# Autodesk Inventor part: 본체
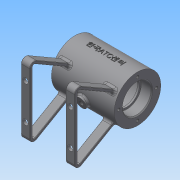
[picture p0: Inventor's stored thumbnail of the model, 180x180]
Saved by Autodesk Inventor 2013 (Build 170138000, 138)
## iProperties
Created: 2016-03
Part Number: 본체
Material: 일반
Document SubType Name: Modeling
Designer: Administrator
Density: 1 g/cm^3
Author: Administrator
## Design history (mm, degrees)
sketch "스케치1"
  geometry: L1 (0, 21)-(21, 21); L2 (21, 21)-(21, 14); L3 (21, 14)-(23, 14); L4 (23, 14)-(23, 16); L5 (23, 16)-(35, 16); L6 (35, 16)-(35, 26); L7 (35, 26)-(0, 26); L8 (0, 26)-(0, 21); L9 (0, 0)-(35, 0)
  constraints: 18 end point, 5 parallel, 3 perpendicular, 1 horizontal, 1 point on line
  dimensions: "d0" = 35 distance of L9.start L9.end; "d2" = 12 distance of L4.end L5.end; "d3" = 2 distance of L2.end L3.end; "d4" = 21 distance of L1.start L1.end; "d6" = 32 diameter of L5 L9; "d7" = 28 diameter of L3 L9; "d8" = 42 diameter of L1 L9; "d9" = 52 diameter of L7 L9
revolve "회전1" sketch "스케치1" stored, may be unused: angle "d10" = 90 deg
sketch "스케치2"
  geometry: C1 r 16 at (0, 0) reference; 1 further point
  constraints: 1 vertical alignment
  dimensions: "d11" = 21 distance of C1.centre point (0, 21)
hole "구멍1" sketch "스케치2" at (0, 21) diameter "d12" = 3.242; stored, may be unused: countersink angle "d16" = 90 deg, drill point angle "d18" = 118 deg; dims "d13" = 8, "d14" = 4, "d15" = 2, "d17" = 10
node "작업 평면1"
sketch "스케치3"
  geometry: L1 (-20, 16.613)-(-57.5, 38.264); L2 (-65, 33.934)-(-65, -33.934); L3 (-57.5, -38.264)-(-20, -16.613); L4 (0, 0)-(-65, 0); L5 (-21.791, 14.183)-(-59, 35.666); L6 (-62, 33.934)-(-62, -33.934); L7 (-59, -35.666)-(-21.791, -14.183); A1 r 26 centre (0, 0) between (-20, 16.613) and (-20, -16.613) reference; A2 r 5 centre (-60, 33.934) between (-57.5, 38.264) and (-65, 33.934); A3 r 5 centre (-60, -33.934) between (-65, -33.934) and (-57.5, -38.264); A4 r 2 centre (-60, 33.934) between (-59, 35.666) and (-62, 33.934); A5 r 2 centre (-60, -33.934) between (-62, -33.934) and (-59, -35.666); 2 further points
  constraints: 14 end point, 12 point on circle, 4 centre point, 4 tangent, 2 point on line, 1 equal radius, 1 horizontal, 1 midpoint, 1 vertical, 4 other
  dimensions: "d23" = 30 deg angle of L4 L3; "d24" = 30 deg angle of L1 L4; "d25" = 45 horizontal distance of point (-65, -42.594) L3.end; "d27" = 65 distance from line of L2 point (0, 0); "d29" = 5 radius of A2; "d30" = 3 distance between parallel lines of L5 L1
extrude "돌출1" join sketch "스케치3" distance "d31" = 10; taper "d32" = 0 deg
sketch "스케치4"
  geometry: L1 (0, 67.868)-(0, 0) reference; L2 (10, 67.868)-(10, 0) reference; 3 further points
  dimensions: "d33" = 20 vertical distance of point (-20, 33.934) point (5, 53.934); "d34" = 20 vertical distance of point (5, 13.934) point (-20, 33.934); "d35" = 5 distance from line of point (5, 53.934) L1; "d36" = 5 distance from line of L2 point (5, 13.934)
hole "구멍2" sketch "스케치4" at (5, 53.934), (5, 13.934) diameter "d37" = 6; stored, may be unused: countersink angle "d41" = 90 deg, drill point angle "d43" = 118 deg; dims "d38" = 8, "d39" = 4, "d40" = 2, "d42" = 6
fillet "모깎기1" dims "d44" = 0.3
fillet "모깎기2" dims "d45" = 3
chamfer "모따기1" distance "d46" = 1; stored, may be unused: second distance "d47" = 2, angle "d48" = 45 deg
fillet "모깎기3" dims "d49" = 0.5
fillet "모깎기4" dims "d50" = 3
node "작업 평면2"
sketch "스케치5"
  geometry: 2 further points
  constraints: 1 coincident, 1 other
feature "엠보싱1" sketch "스케치5" dims "d0" = 35, "d2" = 12, "d3" = 2, "d4" = 21, "d6" = 32, "d7" = 28, "d8" = 42, "d9" = 52, "d52" = 0.5, "d53" = 0
node "작업 평면3"
sketch "스케치6"
  geometry: C1 r 5 at (0, 0); 1 further point
  constraints: 1 centre point, 1 coincident
  dimensions: "d55" = 10 diameter of C1
extrude "돌출2" join sketch "스케치6" stored distance "d56" = 10; taper "d57" = 0 deg
sketch "스케치7"
  geometry: 2 further points
  constraints: 1 coincident
hole "구멍3" sketch "스케치7" at (0, 0) diameter "d58" = 5.188; stored, may be unused: countersink angle "d62" = 90 deg, drill point angle "d64" = 118 deg; dims "d59" = 8, "d60" = 4, "d61" = 2, "d63" = 6
sketch "스케치8"
  geometry: L1 (-64.5, 33.934)-(-64.5, -33.934) reference; L2 (0, 0)-(-64.5, 0); L3 (0, 0)-(-28.012, -7.506)
  constraints: 4 end point, 1 midpoint
  dimensions: "d65" = 29 distance of L2.start L3.end; "d66" = 15 deg angle of L3 L2
node "작업 평면4"
sketch "스케치9"
  geometry: C1 r 6 at (0, 0); 1 further point
  constraints: 1 centre point, 1 coincident
  dimensions: "d67" = 12 diameter of C1
extrude "돌출3" join sketch "스케치9" stored distance "d68" = 10; taper "d69" = 0 deg
sketch "스케치10"
  geometry: 2 further points
  constraints: 1 coincident
hole "구멍4" sketch "스케치10" at (0, 0) diameter "d70" = 5.188; stored, may be unused: countersink angle "d74" = 90 deg, drill point angle "d76" = 118 deg; dims "d71" = 8, "d72" = 4, "d73" = 2, "d75" = 6
fillet "모깎기5" dims "d77" = 2
node "솔리드1"
pattern_circular "원형 패턴1" dims angle "d20" = 360 deg
mirror "대칭1"
other parameters: "d51" = 45.25, "d54" = 29
